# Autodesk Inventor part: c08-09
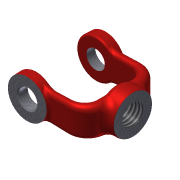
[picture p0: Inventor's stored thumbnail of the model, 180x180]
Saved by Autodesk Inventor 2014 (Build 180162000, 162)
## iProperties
Created: 2010-12
Part Number: c08-09
Material: Iron, Cast
Document SubType Name: Modeling
Designer: Thom Tremblay
Mass: 107.693 g
Surface Area: 70.4564 cm^2
Volume: 14.8541 cm^3
Density: 7.25 g/cm^3
Appearance: Anodized - Red
Author: Thom Tremblay
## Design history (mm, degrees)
sketch "Sketch1"
  geometry: L1 (0, 0)-(0, -19.05); L2 (0, -19.05)-(-38.1, -19.05)
  constraints: 4 end point, 1 perpendicular, 1 vertical
  dimensions: "d0" = 19.05 distance of L1.start L1.end; "d1" = 38.1 distance of L1.end L2.end
workplane "Work Plane1"
sketch "Sketch2"
  geometry: C1 r 12.7 at (-38.1, 0); 2 further points
  constraints: 1 centre point, 1 coincident
  dimensions: "d2" = 25.4 diameter of C1
extrude "Extrusion1" new body sketch "Sketch2" distance "d3" = 7.62; taper "d4" = -2 deg
sketch "Sketch3"
  geometry: L1 (0, 0)-(7.66, 0); L2 (0, -9.525)-(-38.1, -9.525); L3 (-38.1, -9.525)-(-38.1, 9.525); L4 (-38.1, 9.525)-(0, 9.525); L5 (0, 9.525)-(0, -9.525); 3 further points
  constraints: 10 end point, 2 midpoint, 2 parallel, 1 coincident, 1 horizontal, 1 horizontal alignment, 1 perpendicular
  dimensions: "d11" = 19.05 distance of L4.end L2.start
extrude "Extrusion2" join sketch "Sketch3" distance "d12" = 4.7752; taper "d13" = 0 deg
sketch "Sketch4"
  geometry: L1 (29.7, 9.525)-(0, 9.525) reference; L2 (0, 9.525)-(0, -9.525) reference; L3 (0, -9.525)-(29.7, -9.525) reference; L4 (7.62, -9.525)-(7.62, 9.525); 1 further point
  constraints: 2 end point, 2 point on line, 1 perpendicular
  dimensions: "d14" = 7.62 distance between parallel lines of L2 L4
extrude "Extrusion3" join sketch "Sketch4" stored distance "d15" = 4.7752; taper "d16" = 0 deg
feature "FaceDraft1" dims angle "d17" = -2 deg
fillet "Fillet1" dims "d18" = 7.62
fillet "Fillet2" dims "d19" = 12.7
fillet "Fillet5" dims "d20" = 12.7
fillet "Fillet3"
fillet "Fillet4"
fillet "Fillet6" dims "d21" = 2.54
fillet "Fillet7" dims "d22" = 1.27
workplane "Work Plane2"
mirror "Mirror1"
sketch "Sketch5"
  geometry: C1 r 12.7 at (5.58, 11.125); 1 further point
  constraints: 1 centre point, 1 coincident
  dimensions: "d23" = 25.4 diameter of C1
extrude "Extrusion4" join sketch "Sketch5" distance "d24" = 6.35; taper "d25" = 0 deg; dims "d37" = 6.35, "d38" = 0
fillet "Fillet10" dims "d39" = 3.81
fillet "Fillet11" dims "d40" = 6.35
fillet "Fillet12" dims "d41" = 2.54
workplane "Work Plane4"
split "Split3"
split "Split1"
split "Split2"
hole "Hole2" diameter "d44" = 13.3858; stored, may be unused: countersink angle "d48" = 82 deg, drill point angle "d50" = 118 deg; dims "d45" = 19.05, "d46" = 9.525, "d47" = 6.35, "d49" = 25.4, "d69" = 25.4, "d70" = 25.4
hole "Hole3" diameter "d53" = 11.9126; stored, may be unused: countersink angle "d57" = 82 deg, drill point angle "d59" = 118 deg; dims "d54" = 19.05, "d55" = 9.525, "d56" = 9.2456, "d58" = 25.4, "d71" = 25.4, "d72" = 25.4
chamfer "Chamfer1" distance "d62" = 0.762; stored, may be unused: second distance "d63" = 3.175, angle "d64" = 45 deg
body "Solid1"
workplane "Work Plane3"
other parameters: "d67" = -1.27, "d68" = -1.27
